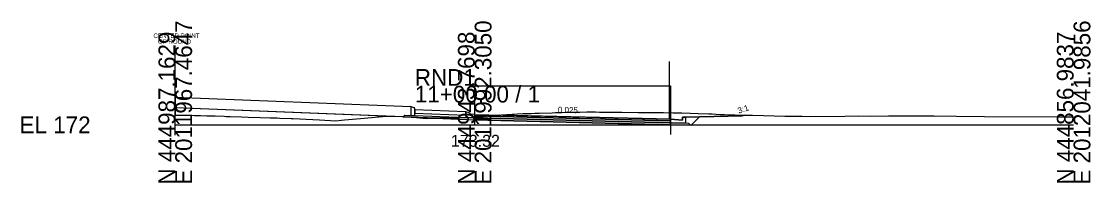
# Model space of a CAD drawing. Extents: x -26 to 153, y -10 to 6017.
# Drawn here: x -25.7 to 152.8, y 1990.3 to 2017.3 of the extents above; entities that cross this region are included whole.
import ezdxf

# ---------------------------------------------------------------- set-up
doc = ezdxf.new("R2010")
doc.units = 0
for name, color, linetype in [('Exist Cross Section Cell', 7, 'Continuous'), ('Exist XS Ground Line', 7, 'Continuous'), ('Prop CMT Conc Surface', 7, 'Continuous'), ('Prop CMT Concrete Structures', 7, 'Continuous'), ('Prop CMT Pvmt Course 1', 7, 'Continuous'), ('Prop CMT Pvmt Course 1 CG', 7, 'Continuous'), ('Prop CMT Pvmt Course 2', 7, 'Continuous'), ('Prop CMT Pvmt Course 3', 7, 'Continuous'), ('Prop CMT Pvmt Surface', 7, 'Continuous'), ('Prop CMT Shear Line', 7, 'Continuous'), ('Prop CMT Shear Line Text', 7, 'Continuous'), ('Prop CMT Slope Grass', 7, 'Continuous'), ('Prop CMT Subgrade Earthwork', 7, 'Continuous'), ('Prop XS Earthwork Shape', 7, 'Continuous'), ('Prop XS SE Text', 7, 'Continuous'), ('Prop XS Side Slope Text', 7, 'Continuous'), ('Scratch_Level_1', 7, 'Continuous')]:
    doc.layers.add(name, color=color, linetype=linetype)

msp = doc.modelspace()

# ---------------------------------------------------------------- linework, layer by layer
at = {"layer": 'Exist Cross Section Cell'}
for p, q in [((50, 2000), (50, 2006.54)), ((0, 2000), (50, 2000)), ((50, 2000), (150, 2000))]:
    msp.add_line(p, q, dxfattribs=at)
at = {"layer": 'Exist XS Ground Line'}
msp.add_lwpolyline([(0, 2001.62), (1.2, 2001.61), (2.6, 2001.59), (3.2, 2001.58), (4.22, 2001.55), (5.29, 2001.51), (6.69, 2001.48), (8.15, 2001.43), (8.52, 2001.42), (9.16, 2001.4), (11.06, 2001.34), (12.19, 2001.3), (14.22, 2001.22), (15.87, 2001.18), (17, 2001.16), (17.48, 2001.14), (19.34, 2001.07), (19.67, 2001.04), (22.98, 2000.9), (24.07, 2000.85), (26.8, 2000.67), (27.75, 2000.76), (28.26, 2000.82), (30.93, 2001.06), (32.75, 2001.23), (35.2, 2001.45), (37.96, 2001.42), (40.28, 2001.24), (41.87, 2001.07), (45.33, 2001.11), (46.44, 2001.13), (47.22, 2001.15), (48.51, 2001.21), (48.88, 2001.23), (49.46, 2001.28), (50, 2001.32), (51.41, 2001.42), (52.52, 2001.5), (54.5, 2001.67), (57.17, 2001.83), (58.01, 2001.87), (59.46, 2001.92), (60.05, 2001.94), (60.83, 2001.96), (62.93, 2002.02), (63.51, 2002.04), (64.53, 2002.07), (65.35, 2002.1), (65.82, 2002.11), (67.53, 2002.14), (68.7, 2002.17), (69.03, 2002.18), (70.18, 2002.15), (70.84, 2002.13), (71.57, 2002.12), (74.57, 2002.11), (77.31, 2002.07), (79.56, 2002.06), (80.09, 2002.06), (80.46, 2002.06), (81.52, 2002.05), (83.07, 2002.02), (84.6, 2001.98), (85.95, 2001.94), (87.3, 2001.92), (89.12, 2001.84), (89.63, 2001.82), (90.98, 2001.75), (91.72, 2001.72), (93.46, 2001.65), (94.04, 2001.63), (94.64, 2001.61), (96.39, 2001.62), (98.21, 2001.57), (101.8, 2001.47), (103.32, 2001.44), (104.67, 2001.43), (106.05, 2001.41), (111.78, 2001.46), (114.04, 2001.48), (116.16, 2001.47), (119.11, 2001.48), (126.7, 2001.48), (130.43, 2001.46), (135.11, 2001.39), (147.48, 2001.34), (150, 2001.31)], dxfattribs=at)
at = {"layer": 'Prop CMT Conc Surface'}
for points in [[(40, 2002.71), (39.96, 2002.82), (39.85, 2002.86), (39.34, 2003.05)], [(40, 2002.55), (40, 2002.71)], [(50, 2001.75), (49.25, 2001.77), (49.25, 2001.94), (48.5, 2002.19)], [(82.71, 2000.93), (84.7, 2000.8)], [(84.7, 2000.8), (84.7, 2001.3), (85.2, 2001.3)]]:
    msp.add_lwpolyline(points, dxfattribs=at)
at = {"layer": 'Prop CMT Concrete Structures'}
for points in [[(40, 2002.71), (39.96, 2002.82), (39.85, 2002.86), (39.34, 2003.05)], [(39.34, 2003.05), (39.34, 2001.55)], [(39.34, 2001.55), (40, 2001.55)], [(40, 2002.55), (40, 2002.71)], [(40, 2001.55), (40, 2002.55)], [(40, 2002.55), (40, 2001.96)], [(48.5, 2002.19), (40, 2002.53)], [(40, 2001.94), (48.5, 2001.6)], [(50, 2001.75), (49.25, 2001.77), (49.25, 2001.94), (48.5, 2002.19)], [(48.5, 2002.19), (48.5, 2001.21)], [(48.5, 2001.6), (48.5, 2002.19)], [(50, 2001.17), (50, 2001.75)], [(48.5, 2001.21), (50, 2001.17)], [(82.71, 2000.93), (84.7, 2000.8), (84.7, 2001.3), (85.2, 2001.3)], [(85.2, 2001.3), (85.2, 2000.28), (82.71, 2000.35)], [(82.71, 2000.35), (82.71, 2000.93)]]:
    msp.add_lwpolyline(points, dxfattribs=at)
at = {"layer": 'Prop CMT Pvmt Course 1'}
for points in [[(50, 2001.75), (82.71, 2000.93)], [(50, 2001.5), (50, 2001.75)], [(82.71, 2000.68), (50, 2001.5)], [(82.71, 2000.93), (82.71, 2000.68)]]:
    msp.add_lwpolyline(points, dxfattribs=at)
msp.add_lwpolyline([(50, 2001.5), (50, 2001.63), (50, 2001.63), (50, 2001.5)], close=True, dxfattribs=at)
at = {"layer": 'Prop CMT Pvmt Course 1 CG'}
for points in [[(50, 2000.83), (50, 2001.17)], [(82.71, 2000.35), (85.69, 2000.27), (86.03, 1999.93)], [(82.71, 2000.01), (82.71, 2000.35)], [(86.12, 1999.93), (82.71, 2000.01)]]:
    msp.add_lwpolyline(points, dxfattribs=at)
at = {"layer": 'Prop CMT Pvmt Course 2'}
for points in [[(50, 2001.17), (50, 2001.5)], [(50, 2001.5), (82.71, 2000.68)], [(82.71, 2000.35), (50, 2001.17)], [(82.71, 2000.68), (82.71, 2000.35)]]:
    msp.add_lwpolyline(points, dxfattribs=at)
at = {"layer": 'Prop CMT Pvmt Course 3'}
for points in [[(40, 2001.55), (48.5, 2001.21)], [(50, 2001.17), (82.71, 2000.35)], [(50, 2000.83), (50, 2001.17)], [(82.71, 2000.01), (50, 2000.83)], [(82.71, 2000.35), (82.71, 2000.01)]]:
    msp.add_lwpolyline(points, dxfattribs=at)
at = {"layer": 'Prop CMT Pvmt Surface'}
msp.add_lwpolyline([(50, 2001.75), (82.71, 2000.93)], dxfattribs=at)
at = {"layer": 'Prop CMT Shear Line'}
msp.add_line((0, 1998.29), (0, 2013.29), dxfattribs=at)
at = {"layer": 'Prop CMT Slope Grass'}
for p, q in [((39.34, 2003.03), (0, 2004.6)), ((38.06, 2001.31), (0, 2002.83))]:
    msp.add_line(p, q, dxfattribs=at)
msp.add_lwpolyline([(85.2, 2001.3), (94.66, 2001.49), (95.02, 2001.61)], dxfattribs=at)
at = {"layer": 'Prop CMT Subgrade Earthwork'}
for p, q in [((0, 2004.6), (0, 2001.62)), ((38.34, 2001.59), (38.06, 2001.31))]:
    msp.add_line(p, q, dxfattribs=at)
for points in [[(38.34, 2001.59), (39.34, 2001.55)], [(38.06, 2001.31), (50, 2000.83)], [(50, 2000.83), (82.71, 2000.01)], [(82.71, 2000.01), (86.12, 1999.93), (87.53, 2001.35)]]:
    msp.add_lwpolyline(points, dxfattribs=at)
at = {"layer": 'Prop XS Earthwork Shape'}
for points in [[(35, 2001.43), (0, 2002.83), (0, 2001.62), (1.2, 2001.61), (2.6, 2001.59), (3.2, 2001.58), (4.22, 2001.55), (5.29, 2001.51), (6.69, 2001.48), (8.15, 2001.43), (8.52, 2001.42), (9.16, 2001.4), (11.06, 2001.34), (12.19, 2001.3), (14.22, 2001.22), (15.87, 2001.18), (17, 2001.16), (17.48, 2001.14), (19.34, 2001.07), (19.67, 2001.04), (22.98, 2000.9), (24.07, 2000.85), (26.8, 2000.67), (27.75, 2000.76), (28.26, 2000.82), (30.93, 2001.06), (32.75, 2001.23)], [(35, 2001.43), (35.2, 2001.45), (37.96, 2001.42), (38.16, 2001.41), (38.06, 2001.31)], [(40.28, 2001.24), (40.55, 2001.21), (38.06, 2001.31), (38.16, 2001.41)], [(43.62, 2001.09), (50, 2000.83), (82.71, 2000.01), (86.12, 1999.93), (87.53, 2001.35), (85.2, 2001.3), (85.2, 2000.28), (82.71, 2000.35), (82.71, 2000.93), (54.2, 2001.64), (52.52, 2001.5), (51.41, 2001.42), (50, 2001.32), (50, 2001.17), (48.5, 2001.21), (47.22, 2001.15), (46.44, 2001.13), (45.33, 2001.11)], [(84.6, 2001.98), (85.95, 2001.94), (87.3, 2001.92), (89.12, 2001.84), (89.63, 2001.82), (90.98, 2001.75), (91.72, 2001.72), (93.46, 2001.65), (94.04, 2001.63), (94.64, 2001.61), (95.02, 2001.61), (94.66, 2001.49), (87.53, 2001.35), (85.2, 2001.3), (84.7, 2001.3), (84.7, 2000.8), (82.71, 2000.93), (54.2, 2001.64), (54.5, 2001.67), (57.17, 2001.83), (58.01, 2001.87), (59.46, 2001.92), (60.05, 2001.94), (60.83, 2001.96), (62.93, 2002.02), (63.51, 2002.04), (64.53, 2002.07), (65.35, 2002.1), (65.82, 2002.11), (67.53, 2002.14), (68.7, 2002.17), (69.03, 2002.18), (70.18, 2002.15), (70.84, 2002.13), (71.57, 2002.12), (74.57, 2002.11), (77.31, 2002.07), (79.56, 2002.06), (80.09, 2002.06), (80.46, 2002.06), (81.52, 2002.05), (83.07, 2002.02)], [(40.55, 2001.21), (41.87, 2001.07), (43.62, 2001.09)], [(48.5, 2001.21), (48.51, 2001.21), (48.88, 2001.23), (49.46, 2001.28), (50, 2001.32), (50, 2001.17)], [(82.71, 2000.93), (84.7, 2000.8), (84.7, 2001.3), (85.2, 2001.3), (85.2, 2000.28), (82.71, 2000.35)]]:
    msp.add_lwpolyline(points, close=True, dxfattribs=at)
at = {"layer": 'Scratch_Level_1'}
msp.add_line((82.51, 2000.95), (82.51, 2010.63), dxfattribs=at)
msp.add_lwpolyline([(50, 2006.54), (82.71, 2006.54), (82.71, 1998.36)], dxfattribs=at)

# ---------------------------------------------------------------- texts
at = {"layer": 'Exist Cross Section Cell'}
for s, p in [('E 2011967.4647', (2.8, 1990)), ('E 2011992.3050', (52.8, 1990)), ('E 2012041.9856', (152.8, 1990)), ('N 444987.1629', (0, 1990)), ('N 444943.7698', (50, 1990)), ('N 444856.9837', (150, 1990))]:
    msp.add_text(s, height=2.8, rotation=90, dxfattribs=at).set_placement(p)
for s, p in [('RND1', (40, 2006.54)), ('11+00.00 / 1', (40, 2003.74)), ('EL 172', (-26, 1998.6))]:
    msp.add_text(s, height=2.8, dxfattribs=at).set_placement(p)
at = {"layer": 'Exist XS Ground Line'}
msp.add_text('173.32', height=2, dxfattribs=at).set_placement((46.03, 1996.32))
at = {"layer": 'Prop CMT Shear Line Text'}
for s, p in [('CENTER POINT', (-3.64, 2014.55)), ('OF ROUND', (-2.88, 2013.57))]:
    msp.add_text(s, height=0.75, dxfattribs=at).set_placement(p)
at = {"layer": 'Prop XS SE Text'}
msp.add_text('0.025', height=1, rotation=358.5613, dxfattribs=at).set_placement((63.87, 2002.03))
at = {"layer": 'Prop XS Side Slope Text'}
msp.add_text('3:1', height=1, rotation=18.4349, dxfattribs=at).set_placement((94.1, 2001.86))

doc.saveas('drawing.dxf')
